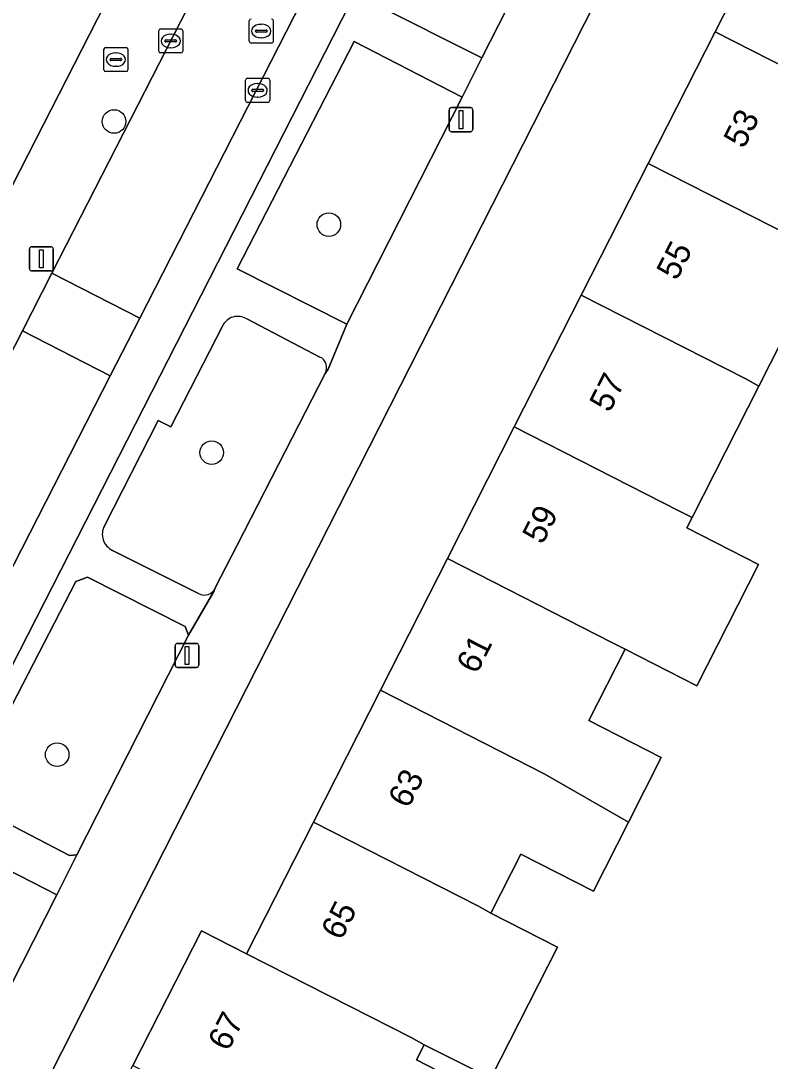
# Model space of a CAD drawing. Extents: x 160349 to 161355, y 381727 to 382854.
# Drawn here: x 160739.81 to 160770.96, y 382263.35 to 382306.55 of the extents above; entities that cross this region are included whole.
import ezdxf

# ---------------------------------------------------------------- set-up
doc = ezdxf.new("R2010")
doc.units = 0
for name, color, linetype in [('IMGEO_Boom', 7, 'Continuous'), ('IMGEO_Brandkraan', 7, 'Continuous'), ('IMGEO_Erf', 7, 'Continuous'), ('IMGEO_Groenvoorziening', 7, 'Continuous'), ('IMGEO_Kolk', 7, 'Continuous'), ('IMGEO_Lichtmast', 7, 'Continuous'), ('IMGEO_Pand', 7, 'Continuous'), ('IMGEO_Pand_nummerreeks', 7, 'Continuous'), ('IMGEO_Parkeervlak_open', 7, 'Continuous'), ('IMGEO_Rijbaan_lokaal_open', 7, 'Continuous'), ('IMGEO_Rioolput', 7, 'Continuous'), ('IMGEO_Voetpad_open', 7, 'Continuous')]:
    doc.layers.add(name, color=color, linetype=linetype)

msp = doc.modelspace()

# ---------------------------------------------------------------- linework, layer by layer
at = {"layer": 'IMGEO_Boom'}
for centre in [(160743.686, 382302.371), (160752.612, 382298.09), (160747.743, 382288.619), (160741.321, 382276.077)]:
    msp.add_circle(centre, 0.489, dxfattribs=at)
at = {"layer": 'IMGEO_Brandkraan'}
for p, q in [((160743.333, 382305.443), (160744.185, 382305.443)), ((160743.258, 382304.517), (160743.258, 382305.369)), ((160743.746, 382305.223), (160743.771, 382305.223)), ((160744.259, 382305.369), (160744.259, 382304.517)), ((160743.517, 382304.937), (160743.517, 382304.949)), ((160743.955, 382304.9), (160743.557, 382304.9)), ((160743.56, 382304.986), (160743.958, 382304.986)), ((160743.769, 382304.663), (160743.744, 382304.663)), ((160744.001, 382304.949), (160744.001, 382304.937)), ((160744.185, 382304.443), (160743.333, 382304.443))]:
    msp.add_line(p, q, dxfattribs=at)
for points in [[(160743.333, 382305.443), (160744.185, 382305.443)], [(160743.258, 382304.517), (160743.258, 382305.369)], [(160744.259, 382305.369), (160744.259, 382304.517)], [(160744.185, 382304.443), (160743.333, 382304.443)]]:
    msp.add_lwpolyline(points, dxfattribs=at)
for centre, radius, start, end in [((160743.335, 382305.367), 0.0765, 91.552, 178.448), ((160743.335, 382305.367), 0.0765, 91.552, 178.448), ((160744.183, 382305.367), 0.0765, 1.552, 88.448), ((160744.183, 382305.367), 0.0765, 1.552, 88.448), ((160743.557, 382304.946), 0.0403, 85.8775, 175.7526), ((160743.554, 382304.936), 0.0366, 178.938, 274.7102), ((160743.958, 382304.943), 0.043, 264.8664, 352.4533), ((160743.962, 382304.948), 0.0386, 1.7309, 96.639), ((160743.335, 382304.519), 0.0765, 181.552, 268.448), ((160743.335, 382304.519), 0.0765, 181.552, 268.448), ((160744.183, 382304.519), 0.0765, 271.552, 358.448), ((160744.183, 382304.519), 0.0765, 271.552, 358.448)]:
    msp.add_arc(centre, radius, start, end, dxfattribs=at)
for centre, major_axis, ratio, start_param, end_param in [((160743.745, 382304.943), (-0.387, 0.002), 0.722429, 4.712389, 7.853982), ((160743.77, 382304.943), (-0.39, 0.002), 0.717154, 1.570796, 4.712389)]:
    msp.add_ellipse(centre, major_axis=major_axis, ratio=ratio, start_param=start_param, end_param=end_param, dxfattribs=at)
at = {"layer": 'IMGEO_Erf'}
for points in [[(160781.126, 382341.611), (160738.964, 382258.729), (160737.898, 382256.951), (160734.312, 382250), (160733.108, 382247.631), (160735.817, 382246.255), (160737.731, 382250), (160738.743, 382251.98), (160741.601, 382257.573), (160744.459, 382263.165), (160747.317, 382268.759), (160749.187, 382267.808), (160751.97, 382273.278), (160754.753, 382278.749), (160757.536, 382284.218), (160760.319, 382289.688), (160763.102, 382295.158), (160765.885, 382300.628), (160768.667, 382306.097), (160771.451, 382311.568)], [(160771.9, 382294.163), (160770.485, 382291.382), (160767.71, 382285.928), (160767.488, 382285.491), (160770.468, 382283.975), (160767.905, 382278.937), (160764.925, 382280.453), (160763.417, 382277.49), (160766.428, 382275.957), (160765.066, 382273.279), (160763.607, 382270.411), (160760.596, 382271.944), (160759.348, 382269.49), (160762.111, 382268.084), (160759.343, 382262.644), (160756.567, 382264.025), (160756.251, 382263.404), (160757.139, 382262.952)]]:
    msp.add_lwpolyline(points, dxfattribs=at)
msp.add_lwpolyline([(160755.792, 382331.673), (160754.104, 382332.518), (160751.377, 382333.881), (160748.416, 382328.085), (160745.525, 382322.427), (160742.634, 382316.767), (160739.742, 382311.107), (160736.851, 382305.448), (160733.96, 382299.79), (160731.069, 382294.13), (160728.177, 382288.471), (160725.286, 382282.812), (160722.395, 382277.152), (160719.504, 382271.493), (160716.613, 382265.834), (160713.721, 382260.174), (160710.767, 382254.392), (160715.129, 382252.163)], close=True, dxfattribs=at)
at = {"layer": 'IMGEO_Groenvoorziening'}
for points in [[(160758.975, 382305.009), (160762.822, 382312.572), (160763.858, 382314.619), (160759.393, 382316.858), (160754.468, 382307.275)], [(160753.354, 382293.959), (160758.146, 382303.38), (160753.658, 382305.698), (160748.804, 382296.252)], [(160746.779, 382281.034), (160746.64, 382281.398), (160742.576, 382283.446), (160742.094, 382283.27), (160737.459, 382274.316), (160737.593, 382274.088), (160741.834, 382271.895), (160742.138, 382271.911)], [(160741.3, 382270.262), (160736.629, 382272.655), (160731.809, 382263.052), (160731.686, 382262.814), (160736.339, 382260.512), (160736.425, 382260.679)]]:
    msp.add_lwpolyline(points, close=True, dxfattribs=at)
for points in [[(160748.187, 382293.871), (160746.038, 382289.688), (160745.52, 382289.955), (160743.284, 382285.585)], [(160752.242, 382292.589), (160749.204, 382294.172)], [(160747.891, 382283.002), (160748.796, 382284.772), (160751.087, 382289.236), (160752.454, 382291.906)], [(160743.622, 382284.562), (160747.196, 382282.767)]]:
    msp.add_lwpolyline(points, dxfattribs=at)
for centre, radius, start, end in [((160748.829, 382293.571), 0.708, 58.0216, 154.9526), ((160752.028, 382292.148), 0.49, 330.3617, 64.1265), ((160743.936, 382285.233), 0.741, 151.6584, 244.9088), ((160747.436, 382283.203), 0.498, 241.2054, 336.1584)]:
    msp.add_arc(centre, radius, start, end, dxfattribs=at)
at = {"layer": 'IMGEO_Kolk'}
for p, q in [((160745.539, 382305.29), (160745.539, 382306.142)), ((160745.614, 382306.216), (160746.466, 382306.216)), ((160746.027, 382305.996), (160746.052, 382305.996)), ((160746.54, 382306.142), (160746.54, 382305.29)), ((160745.798, 382305.71), (160745.798, 382305.722)), ((160746.236, 382305.673), (160745.838, 382305.673)), ((160745.841, 382305.759), (160746.239, 382305.759)), ((160746.282, 382305.722), (160746.282, 382305.71)), ((160746.466, 382305.216), (160745.614, 382305.216)), ((160746.05, 382305.436), (160746.025, 382305.436)), ((160749.227, 382304.164), (160750.079, 382304.164)), ((160749.152, 382303.238), (160749.152, 382304.09)), ((160749.64, 382303.944), (160749.665, 382303.944)), ((160750.153, 382304.09), (160750.153, 382303.238)), ((160749.411, 382303.658), (160749.411, 382303.67)), ((160749.849, 382303.621), (160749.451, 382303.621)), ((160749.454, 382303.707), (160749.852, 382303.707)), ((160749.663, 382303.384), (160749.638, 382303.384)), ((160749.895, 382303.67), (160749.895, 382303.658)), ((160750.079, 382303.164), (160749.227, 382303.164))]:
    msp.add_line(p, q, dxfattribs=at)
for points in [[(160745.539, 382305.29), (160745.539, 382306.142)], [(160745.614, 382306.216), (160746.466, 382306.216)], [(160746.54, 382306.142), (160746.54, 382305.29)], [(160746.466, 382305.216), (160745.614, 382305.216)], [(160749.227, 382304.164), (160750.079, 382304.164)], [(160749.152, 382303.238), (160749.152, 382304.09)], [(160750.153, 382304.09), (160750.153, 382303.238)], [(160750.079, 382303.164), (160749.227, 382303.164)]]:
    msp.add_lwpolyline(points, dxfattribs=at)
for centre, radius, start, end in [((160745.616, 382306.14), 0.0765, 91.552, 178.448), ((160745.616, 382306.14), 0.0765, 91.552, 178.448), ((160746.464, 382306.14), 0.0765, 1.552, 88.448), ((160746.464, 382306.14), 0.0765, 1.552, 88.448), ((160745.838, 382305.719), 0.0403, 85.8775, 175.7526), ((160745.835, 382305.709), 0.0366, 178.938, 274.7102), ((160746.239, 382305.716), 0.043, 264.8664, 352.4533), ((160746.243, 382305.721), 0.0386, 1.7309, 96.639), ((160745.616, 382305.292), 0.0765, 181.552, 268.448), ((160745.616, 382305.292), 0.0765, 181.552, 268.448), ((160746.464, 382305.292), 0.0765, 271.552, 358.448), ((160746.464, 382305.292), 0.0765, 271.552, 358.448), ((160749.229, 382304.088), 0.0765, 91.552, 178.448), ((160749.229, 382304.088), 0.0765, 91.552, 178.448), ((160750.077, 382304.088), 0.0765, 1.552, 88.448), ((160750.077, 382304.088), 0.0765, 1.552, 88.448), ((160749.451, 382303.667), 0.0403, 85.8775, 175.7526), ((160749.448, 382303.657), 0.0366, 178.938, 274.7102), ((160749.852, 382303.664), 0.043, 264.8664, 352.4533), ((160749.856, 382303.669), 0.0386, 1.7309, 96.639), ((160749.229, 382303.24), 0.0765, 181.552, 268.448), ((160749.229, 382303.24), 0.0765, 181.552, 268.448), ((160750.077, 382303.24), 0.0765, 271.552, 358.448), ((160750.077, 382303.24), 0.0765, 271.552, 358.448)]:
    msp.add_arc(centre, radius, start, end, dxfattribs=at)
for centre, major_axis, ratio, start_param, end_param in [((160746.026, 382305.716), (-0.387, 0.002), 0.722429, 4.712389, 7.853982), ((160746.051, 382305.716), (-0.39, 0.002), 0.717154, 1.570796, 4.712389), ((160749.639, 382303.664), (-0.387, 0.002), 0.722429, 4.712389, 7.853982), ((160749.664, 382303.664), (-0.39, 0.002), 0.717154, 1.570796, 4.712389)]:
    msp.add_ellipse(centre, major_axis=major_axis, ratio=ratio, start_param=start_param, end_param=end_param, dxfattribs=at)
at = {"layer": 'IMGEO_Lichtmast'}
for p, q in [((160757.706, 382302.947), (160758.496, 382302.947)), ((160758.496, 382302.947), (160757.706, 382302.947)), ((160757.606, 382302.047), (160757.606, 382302.847)), ((160757.606, 382302.847), (160757.606, 382302.047)), ((160758.596, 382302.847), (160758.596, 382302.047)), ((160758.596, 382302.047), (160758.596, 382302.847)), ((160758.496, 382301.947), (160757.706, 382301.947)), ((160757.706, 382301.947), (160758.496, 382301.947)), ((160740.169, 382296.267), (160740.169, 382297.067)), ((160740.169, 382297.067), (160740.169, 382296.267)), ((160740.269, 382297.167), (160741.059, 382297.167)), ((160741.059, 382297.167), (160740.269, 382297.167)), ((160741.159, 382297.067), (160741.159, 382296.267)), ((160741.159, 382296.267), (160741.159, 382297.067)), ((160741.059, 382296.167), (160740.269, 382296.167)), ((160740.269, 382296.167), (160741.059, 382296.167)), ((160746.218, 382279.798), (160746.218, 382280.598)), ((160746.218, 382280.598), (160746.218, 382279.798)), ((160746.318, 382280.698), (160747.108, 382280.698)), ((160747.108, 382280.698), (160746.318, 382280.698)), ((160747.208, 382280.598), (160747.208, 382279.798)), ((160747.208, 382279.798), (160747.208, 382280.598)), ((160747.108, 382279.698), (160746.318, 382279.698)), ((160746.318, 382279.698), (160747.108, 382279.698))]:
    msp.add_line(p, q, dxfattribs=at)
for points in [[(160758.026, 382302.822), (160758.176, 382302.822), (160758.176, 382302.072), (160758.026, 382302.072), (160758.026, 382302.822)], [(160740.589, 382297.042), (160740.739, 382297.042), (160740.739, 382296.292), (160740.589, 382296.292), (160740.589, 382297.042)], [(160746.638, 382280.573), (160746.788, 382280.573), (160746.788, 382279.823), (160746.638, 382279.823), (160746.638, 382280.573)]]:
    msp.add_lwpolyline(points, dxfattribs=at)
for centre, start, end in [((160757.706, 382302.847), 90, 180), ((160757.706, 382302.847), 90, 180), ((160758.496, 382302.847), 0, 90), ((160758.496, 382302.847), 360, 90), ((160757.706, 382302.047), 180, 270), ((160757.706, 382302.047), 180, 270), ((160758.496, 382302.047), 270, 0), ((160758.496, 382302.047), 270, 0), ((160740.269, 382297.067), 90, 180), ((160740.269, 382297.067), 90, 180), ((160741.059, 382297.067), 0, 90), ((160741.059, 382297.067), 360, 90), ((160740.269, 382296.267), 180, 270), ((160740.269, 382296.267), 180, 270), ((160741.059, 382296.267), 270, 0), ((160741.059, 382296.267), 270, 0), ((160746.318, 382280.598), 90, 180), ((160746.318, 382280.598), 90, 180), ((160747.108, 382280.598), 0, 90), ((160747.108, 382280.598), 360, 90), ((160746.318, 382279.798), 180, 270), ((160746.318, 382279.798), 180, 270), ((160747.108, 382279.798), 270, 0), ((160747.108, 382279.798), 270, 0)]:
    msp.add_arc(centre, 0.1, start, end, dxfattribs=at)
at = {"layer": 'IMGEO_Pand'}
for points in [[(160768.667, 382306.097), (160775.503, 382302.618), (160776.056, 382302.333), (160778.291, 382301.193), (160781.081, 382306.667), (160778.841, 382307.807), (160771.451, 382311.568)], [(160765.885, 382300.628), (160772.721, 382297.149), (160773.271, 382296.858), (160776.056, 382302.333), (160775.503, 382302.618), (160768.667, 382306.097)], [(160773.271, 382296.858), (160772.721, 382297.149), (160765.885, 382300.628), (160763.102, 382295.158), (160769.939, 382291.678), (160770.485, 382291.382), (160771.9, 382294.163), (160773.528, 382293.334), (160774.756, 382295.748), (160773.128, 382296.576)], [(160767.71, 382285.928), (160770.485, 382291.382), (160769.939, 382291.678), (160763.102, 382295.158), (160760.319, 382289.688), (160767.157, 382286.208)], [(160767.71, 382285.928), (160767.157, 382286.208), (160760.319, 382289.688), (160757.536, 382284.218), (160764.375, 382280.738), (160764.925, 382280.453), (160767.905, 382278.937), (160770.468, 382283.975), (160767.488, 382285.491)], [(160765.066, 382273.279), (160766.428, 382275.957), (160763.417, 382277.49), (160764.925, 382280.453), (160764.375, 382280.738), (160757.536, 382284.218), (160754.753, 382278.749), (160761.593, 382275.268)], [(160759.348, 382269.49), (160760.596, 382271.944), (160763.607, 382270.411), (160765.066, 382273.279), (160761.593, 382275.268), (160754.753, 382278.749), (160751.97, 382273.278), (160758.81, 382269.798)], [(160759.348, 382269.49), (160758.81, 382269.798), (160751.97, 382273.278), (160749.187, 382267.808), (160756.029, 382264.329), (160756.567, 382264.025), (160759.343, 382262.644), (160762.111, 382268.084)], [(160749.187, 382267.808), (160747.317, 382268.759), (160744.459, 382263.165), (160751.371, 382259.634), (160751.878, 382259.337), (160754.623, 382257.973), (160757.139, 382262.952), (160756.251, 382263.404), (160756.567, 382264.025), (160756.029, 382264.329)]]:
    msp.add_lwpolyline(points, close=True, dxfattribs=at)
at = {"layer": 'IMGEO_Parkeervlak_open'}
for points in [[(160770.321, 382344.149), (160770.391, 382344.334), (160744.752, 382294.201), (160743.527, 382291.806), (160722.147, 382250), (160709.35, 382224.998)], [(160712.131, 382226.605), (160724.188, 382250), (160728.771, 382258.894), (160763.426, 382326.742), (160770.626, 382340.985)]]:
    msp.add_lwpolyline(points, dxfattribs=at)
at = {"layer": 'IMGEO_Rijbaan_lokaal_open'}
for points in [[(160770.391, 382344.334), (160770.943, 382345.399), (160767.303, 382347.242), (160741.101, 382296.066), (160744.752, 382294.201)], [(160741.101, 382296.066), (160739.875, 382293.672), (160743.527, 382291.806), (160744.752, 382294.201)], [(160739.875, 382293.672), (160718.788, 382252.487), (160717.502, 382250), (160717.222, 382249.458), (160707.001, 382229.593), (160704.228, 382224.198), (160707.84, 382222.072), (160709.35, 382224.998), (160722.147, 382250), (160743.527, 382291.806)]]:
    msp.add_lwpolyline(points, close=True, dxfattribs=at)
at = {"layer": 'IMGEO_Rioolput'}
for p, q in [((160749.303, 382305.7), (160749.303, 382306.552)), ((160749.791, 382306.406), (160749.816, 382306.406)), ((160750.304, 382306.552), (160750.304, 382305.7)), ((160749.562, 382306.12), (160749.562, 382306.132)), ((160750, 382306.083), (160749.602, 382306.083)), ((160749.605, 382306.169), (160750.003, 382306.169)), ((160750.046, 382306.132), (160750.046, 382306.12)), ((160750.23, 382305.626), (160749.378, 382305.626)), ((160749.814, 382305.846), (160749.789, 382305.846))]:
    msp.add_line(p, q, dxfattribs=at)
for points in [[(160749.303, 382305.7), (160749.303, 382306.552)], [(160750.304, 382306.552), (160750.304, 382305.7)], [(160750.23, 382305.626), (160749.378, 382305.626)]]:
    msp.add_lwpolyline(points, dxfattribs=at)
for centre, radius, start, end in [((160749.38, 382306.55), 0.0765, 91.552, 178.448), ((160749.38, 382306.55), 0.0765, 91.552, 178.448), ((160750.228, 382306.55), 0.0765, 1.552, 88.448), ((160750.228, 382306.55), 0.0765, 1.552, 88.448), ((160749.602, 382306.129), 0.0403, 85.8775, 175.7526), ((160749.599, 382306.119), 0.0366, 178.938, 274.7102), ((160750.003, 382306.126), 0.043, 264.8664, 352.4533), ((160750.007, 382306.131), 0.0386, 1.7309, 96.639), ((160749.38, 382305.702), 0.0765, 181.552, 268.448), ((160749.38, 382305.702), 0.0765, 181.552, 268.448), ((160750.228, 382305.702), 0.0765, 271.552, 358.448), ((160750.228, 382305.702), 0.0765, 271.552, 358.448)]:
    msp.add_arc(centre, radius, start, end, dxfattribs=at)
for centre, major_axis, ratio, start_param, end_param in [((160749.79, 382306.126), (-0.387, 0.002), 0.722429, 4.712389, 7.853982), ((160749.815, 382306.126), (-0.39, 0.002), 0.717154, 1.570796, 4.712389)]:
    msp.add_ellipse(centre, major_axis=major_axis, ratio=ratio, start_param=start_param, end_param=end_param, dxfattribs=at)
at = {"layer": 'IMGEO_Voetpad_open'}
for points in [[(160717.222, 382249.458), (160717.502, 382250), (160718.788, 382252.487), (160739.875, 382293.672), (160741.101, 382296.066), (160767.303, 382347.242), (160768.273, 382349.143), (160764.998, 382350.801), (160763.498, 382351.061), (160765.081, 382350.252), (160756.469, 382333.026), (160755.792, 382331.673), (160715.129, 382252.163), (160714.493, 382250.92), (160712.637, 382251.813), (160711.717, 382250), (160702.34, 382231.516), (160707.001, 382229.593)], [(160752.454, 382291.906), (160752.579, 382292.088), (160753.354, 382293.959), (160748.804, 382296.252), (160753.658, 382305.698), (160758.146, 382303.38), (160758.975, 382305.009), (160754.468, 382307.275), (160759.393, 382316.858), (160763.858, 382314.619), (160764.623, 382316.13), (160760.193, 382318.413), (160764.996, 382327.759), (160769.395, 382325.56), (160770.077, 382326.909), (160765.691, 382329.113), (160775.257, 382348.083), (160774.537, 382348.455), (160773.986, 382347.417), (160772.475, 382348.182), (160772.004, 382347.255), (160770.943, 382345.399), (160770.391, 382344.334), (160770.321, 382344.149)], [(160779.938, 382345.646), (160770.077, 382326.909), (160769.395, 382325.56), (160764.623, 382316.13), (160763.858, 382314.619), (160762.822, 382312.572), (160758.975, 382305.009), (160758.146, 382303.38), (160753.354, 382293.959), (160752.579, 382292.088), (160752.454, 382291.906), (160751.087, 382289.236), (160748.796, 382284.772), (160747.891, 382283.002), (160747.831, 382282.848), (160746.779, 382281.034), (160742.138, 382271.911), (160741.3, 382270.262), (160736.425, 382260.679)], [(160738.964, 382258.729), (160781.126, 382341.611)], [(160770.626, 382340.985), (160763.426, 382326.742), (160728.771, 382258.894), (160724.188, 382250), (160712.131, 382226.605)], [(160743.284, 382285.585), (160745.52, 382289.955), (160746.038, 382289.688), (160748.187, 382293.871)], [(160749.204, 382294.172), (160752.242, 382292.589)], [(160747.196, 382282.767), (160743.622, 382284.562)], [(160711.687, 382223.83), (160718.48, 382236.882), (160719.15, 382238.159), (160724.629, 382248.896), (160725.775, 382251.147), (160731.022, 382261.484), (160735.635, 382259.125), (160736.339, 382260.512), (160731.686, 382262.814), (160731.809, 382263.052), (160736.629, 382272.655), (160741.3, 382270.262), (160742.138, 382271.911), (160741.834, 382271.895), (160737.593, 382274.088), (160737.459, 382274.316), (160742.094, 382283.27), (160742.576, 382283.446), (160746.64, 382281.398), (160746.779, 382281.034), (160747.831, 382282.848), (160747.891, 382283.002)]]:
    msp.add_lwpolyline(points, dxfattribs=at)
for centre, radius, start, end in [((160748.829, 382293.571), 0.708, 58.0216, 154.9526), ((160752.028, 382292.148), 0.49, 330.3617, 64.1265), ((160743.936, 382285.233), 0.741, 151.6584, 244.9088), ((160747.436, 382283.203), 0.498, 241.2054, 336.1584)]:
    msp.add_arc(centre, radius, start, end, dxfattribs=at)

# ---------------------------------------------------------------- texts
at = {"layer": 'IMGEO_Pand_nummerreeks'}
for s, rotation, p in [('53', 63.0342, (160769.859, 382301.205)), ('55', 63.0368, (160767.071, 382295.725)), ('57', 63.0342, (160764.282, 382290.245)), ('59', 63.0368, (160761.494, 382284.765)), ('61', 63.0342, (160758.757, 382279.385)), ('63', 63.0342, (160755.918, 382273.804)), ('65', 63.0368, (160753.13, 382268.324)), ('67', 62.932, (160748.425, 382263.717))]:
    msp.add_text(s, height=1, rotation=rotation, dxfattribs=at).set_placement(p)

doc.saveas('drawing.dxf')
